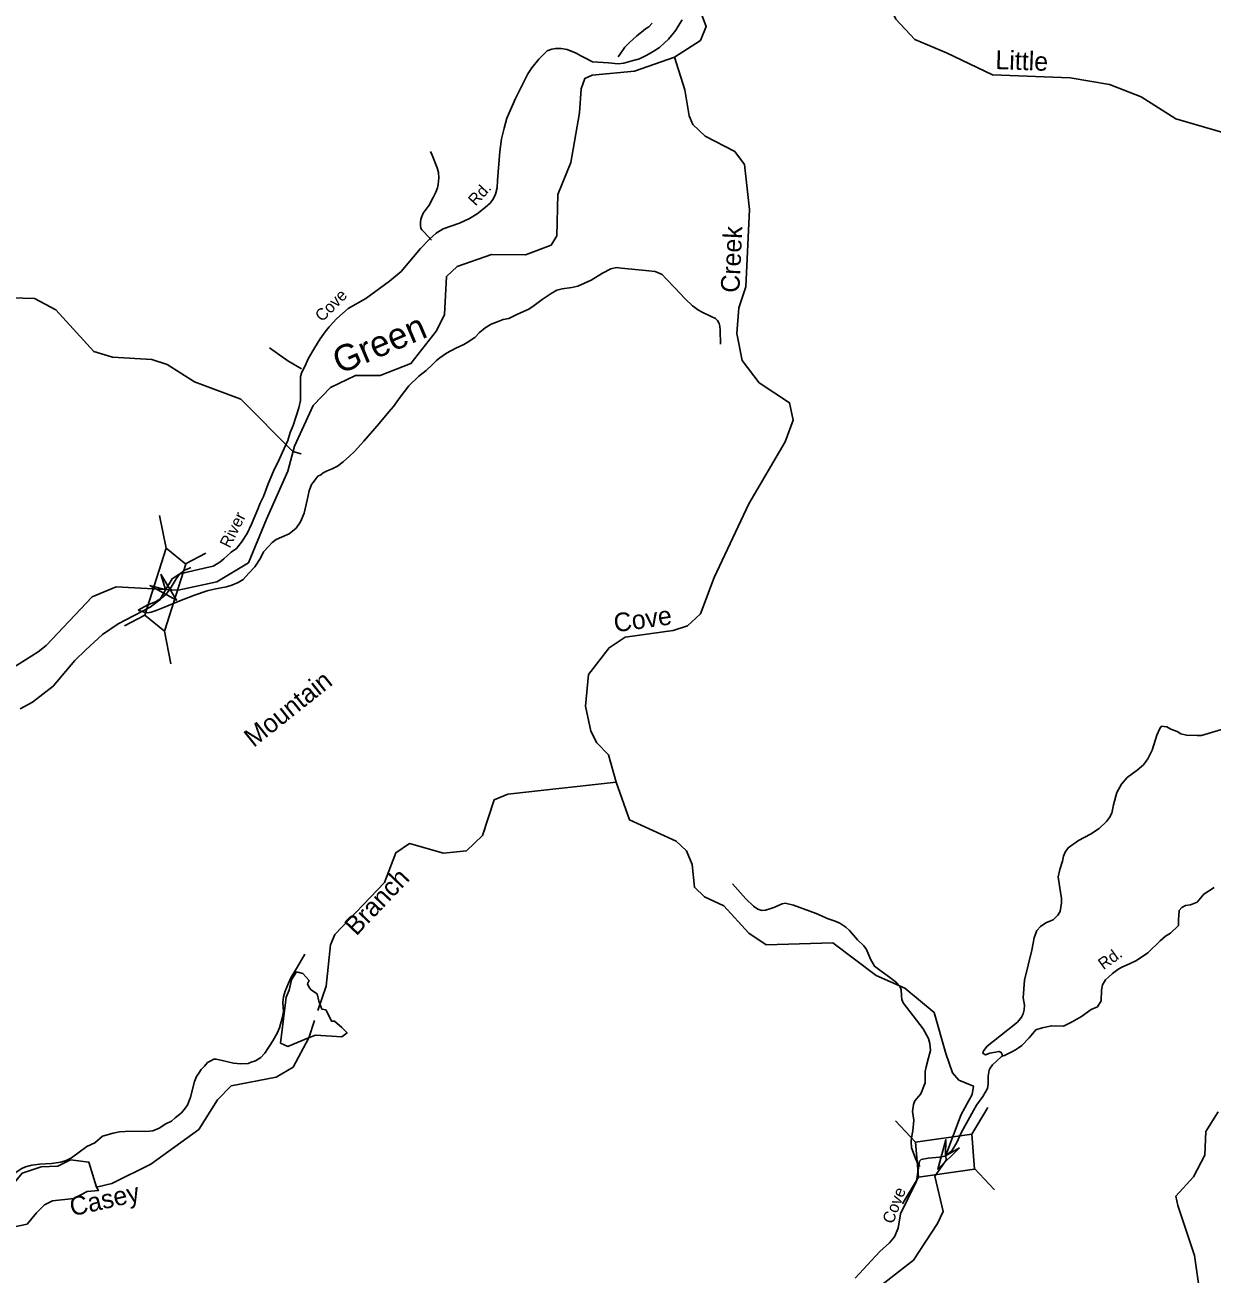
# Model space of a CAD drawing. Extents: x 990631 to 1056237, y 535999 to 585651.
# Drawn here: x 1012421 to 1021960, y 565608 to 575643 of the extents above; entities that cross this region are included whole.
import ezdxf

# ---------------------------------------------------------------- set-up
doc = ezdxf.new("R2010")
doc.units = 0
for name, color, linetype in [('Exist Geographical Mountain Summit Label', 7, 'Continuous'), ('Exist Hydrographic Creek Single Shore', 7, 'Continuous'), ('Exist Hydrographic Creek Single Shore Label', 7, 'Continuous'), ('Exist Hydrographic Pond Over 1500 Sq Ft', 7, 'Continuous'), ('Exist Hydrographic Pond Under 1500 Sq Ft', 7, 'Continuous'), ('Exist Hydrographic River Shore', 7, 'Continuous'), ('Exist Hydrographic River Shore Label', 7, 'Continuous'), ('Exist Road Non-System Type 51', 7, 'Continuous'), ('Exist Road Secondary Structure Standard Bridge Attributed CELL', 7, 'Continuous'), ('Exist Road Secondary Structure Standard Bridge CELL', 7, 'Continuous'), ('Exist Road Secondary Type 41 Attributed', 7, 'Continuous'), ('Exist Road Secondary Type 51 Attributed', 7, 'Continuous'), ('Exist Road Secondary Type 51 Label', 7, 'Continuous')]:
    doc.layers.add(name, color=color, linetype=linetype)

msp = doc.modelspace()

# ---------------------------------------------------------------- linework, layer by layer
at = {"layer": 'Exist Hydrographic Creek Single Shore'}
for points in [[(1023226, 574096), (1023161, 574140), (1023081, 574234), (1022486, 574403), (1022213, 574731), (1021668, 574889), (1021391, 575065), (1021135, 575166), (1020820, 575218), (1020196, 575241), (1019826, 575419), (1019573, 575526), (1019420, 575689), (1019334, 575871), (1019301, 576117), (1019331, 576173), (1019367, 576200), (1019424, 576326), (1019400, 576353), (1019307, 576346), (1019264, 576419), (1019268, 576481)], [(1017171, 569561), (1017111, 569779), (1017015, 569876), (1016968, 569969), (1016924, 570170), (1016950, 570426), (1017115, 570639), (1017243, 570725), (1017629, 570779), (1017746, 570817), (1017850, 570913), (1017960, 571203), (1018238, 571795), (1018530, 572294), (1018594, 572467), (1018565, 572608), (1018320, 572768), (1018184, 572948), (1018142, 573165), (1018157, 573371), (1018213, 573538), (1018242, 574161), (1018204, 574523), (1018124, 574626), (1017886, 574749), (1017789, 574843), (1017758, 574912), (1017723, 575123), (1017640, 575384)], [(1014641, 572198), (1014574, 572216), (1014155, 572638), (1013784, 572777), (1013564, 572916), (1013440, 572955), (1013124, 572974), (1012975, 573020), (1012670, 573354), (1012497, 573446), (1012023, 573459)], [(1014774, 567726), (1014840, 567921), (1014876, 568252), (1014912, 568337), (1015309, 568755), (1015401, 568993), (1015512, 569066), (1015784, 568989), (1015968, 569008), (1016097, 569130), (1016190, 569417), (1016300, 569464), (1017171, 569561)], [(1017782, 568899), (1017736, 569008), (1017655, 569085), (1017278, 569257), (1017171, 569561)], [(1014774, 567726), (1014840, 567921), (1014876, 568252), (1014912, 568337), (1015309, 568755), (1015401, 568993), (1015512, 569066), (1015784, 568989), (1015968, 569008), (1016097, 569130), (1016115, 569184)], [(1017782, 568899), (1017736, 569008), (1017655, 569085), (1017438, 569184)], [(1019174, 565382), (1019210, 565447), (1019561, 565719), (1019754, 566014), (1019799, 566111), (1019733, 566394), (1019823, 566522), (1019820, 566562), (1019943, 566890), (1020033, 567051), (1020043, 567118), (1019926, 567166), (1019875, 567224), (1019820, 567381), (1019727, 567708), (1019492, 567906), (1019262, 568006), (1018912, 568269), (1018378, 568254), (1018239, 568348), (1018038, 568566), (1017882, 568638), (1017801, 568715), (1017782, 568899)], [(1019174, 565382), (1019210, 565447), (1019561, 565719), (1019754, 566014), (1019799, 566111), (1019733, 566394), (1019823, 566522), (1019820, 566562), (1019943, 566890), (1020033, 567051), (1020043, 567118), (1019926, 567166), (1019875, 567224), (1019820, 567381), (1019727, 567708), (1019492, 567906), (1019262, 568006), (1018912, 568269), (1018378, 568254), (1018239, 568348), (1018038, 568566), (1017882, 568638), (1017801, 568715), (1017782, 568899)], [(1014701, 567507), (1014747, 567646)], [(1014701, 567507), (1014747, 567646)], [(1012996, 566307), (1013119, 566335), (1013433, 566492), (1013817, 566770), (1013967, 567007), (1014079, 567119), (1014440, 567191), (1014576, 567270), (1014701, 567507)], [(1012996, 566307), (1013119, 566335), (1013433, 566492), (1013817, 566770), (1013967, 567007), (1014079, 567119), (1014440, 567191), (1014576, 567270), (1014701, 567507)]]:
    msp.add_lwpolyline(points, dxfattribs=at)
at = {"layer": 'Exist Hydrographic Pond Over 1500 Sq Ft'}
msp.add_lwpolyline([(1014475, 567463), (1014533, 567437), (1014698, 567507), (1014755, 567526), (1014883, 567520), (1014966, 567514), (1015010, 567545), (1014966, 567590), (1014908, 567641), (1014883, 567641), (1014864, 567686), (1014838, 567730), (1014806, 567737), (1014781, 567800), (1014768, 567858), (1014724, 567889), (1014704, 567909), (1014692, 567940), (1014704, 567966), (1014654, 568023), (1014603, 568036), (1014564, 567972), (1014545, 567889), (1014520, 567832)], close=True, dxfattribs=at)
at = {"layer": 'Exist Hydrographic Pond Under 1500 Sq Ft'}
msp.add_lwpolyline([(1012996, 566307), (1012934, 566507), (1012788, 566526), (1012686, 566475), (1012552, 566469), (1012399, 566418), (1012323, 566328), (1012227, 566284), (1012138, 566182), (1012132, 566099), (1012176, 566086), (1012221, 566125), (1012272, 566118), (1012240, 566074), (1012234, 566029), (1012285, 565984), (1012323, 565984), (1012438, 566010), (1012514, 566099), (1012578, 566163), (1012641, 566195), (1012813, 566214), (1012921, 566271), (1013011, 566278)], close=True, dxfattribs=at)
at = {"layer": 'Exist Hydrographic River Shore'}
for points in [[(1017640, 575384), (1017849, 575518), (1017896, 575631), (1017849, 575751), (1017884, 575838), (1018048, 576021), (1018164, 576082)], [(1014588, 572258), (1014738, 572585), (1014876, 572730), (1015077, 572826), (1015276, 572826), (1015522, 572922), (1015727, 573185), (1015793, 573318), (1015807, 573623), (1015893, 573703), (1016170, 573799), (1016443, 573796), (1016649, 573875), (1016696, 573948), (1016702, 574280), (1016808, 574539), (1016877, 574937), (1016891, 575130), (1016920, 575213), (1016980, 575239), (1017318, 575273), (1017640, 575384)], [(1012272, 570446), (1012528, 570607), (1012591, 570659), (1012962, 571050), (1013154, 571130), (1013652, 571103), (1013964, 571169), (1014216, 571322), (1014362, 571674), (1014534, 572059), (1014588, 572258)]]:
    msp.add_lwpolyline(points, dxfattribs=at)
at = {"layer": 'Exist Road Non-System Type 51'}
for points in [[(1017462, 575657), (1017433, 575628), (1017407, 575611), (1017374, 575586), (1017339, 575555), (1017277, 575499), (1017242, 575465), (1017202, 575406), (1017189, 575386)], [(1015687, 573915), (1015625, 573980), (1015610, 573998), (1015602, 574010), (1015599, 574030), (1015598, 574060), (1015603, 574084), (1015622, 574130), (1015668, 574196), (1015701, 574257), (1015722, 574301), (1015737, 574334), (1015742, 574362), (1015746, 574416), (1015743, 574458), (1015734, 574494), (1015692, 574596), (1015679, 574626)], [(1018009, 573079), (1018008, 573190), (1018006, 573222), (1018000, 573244), (1017985, 573268), (1017970, 573285), (1017936, 573302), (1017863, 573335), (1017834, 573351), (1017785, 573387), (1017727, 573443), (1017643, 573532), (1017572, 573606), (1017541, 573639), (1017484, 573663), (1017434, 573669), (1017298, 573681), (1017211, 573690), (1017175, 573694), (1017130, 573683), (1017061, 573649), (1016971, 573592), (1016918, 573568), (1016864, 573544), (1016815, 573534), (1016739, 573522), (1016696, 573512), (1016649, 573485), (1016578, 573437), (1016512, 573390), (1016469, 573359), (1016380, 573320), (1016309, 573286), (1016264, 573278), (1016210, 573256), (1016167, 573239), (1016118, 573209), (1016073, 573172), (1016035, 573133), (1015974, 573093), (1015947, 573076), (1015882, 573046), (1015809, 573005), (1015756, 572970), (1015729, 572947), (1015692, 572913), (1015646, 572868), (1015587, 572822), (1015506, 572743), (1015435, 572653), (1015382, 572579), (1015345, 572536), (1015268, 572440), (1015145, 572298), (1015070, 572217), (1015029, 572178), (1014977, 572132), (1014932, 572099), (1014889, 572077), (1014849, 572062), (1014818, 572045), (1014798, 572030), (1014775, 572019), (1014757, 571997), (1014736, 571968), (1014723, 571950), (1014705, 571899), (1014689, 571825), (1014665, 571720), (1014635, 571651), (1014599, 571600), (1014572, 571577), (1014544, 571554), (1014481, 571528), (1014440, 571509), (1014407, 571485), (1014380, 571457), (1014339, 571409), (1014313, 571360), (1014269, 571289), (1014221, 571240), (1014173, 571188), (1014134, 571163), (1014084, 571143), (1014041, 571130), (1013940, 571110), (1013884, 571098), (1013783, 571063), (1013651, 571011), (1013543, 570965), (1013476, 570939), (1013436, 570925), (1013408, 570919), (1013386, 570922), (1013330, 570942)], [(1014387, 573048), (1014532, 572945), (1014644, 572881)], [(1013330, 570942), (1013408, 570984), (1013469, 571009), (1013520, 571040), (1013555, 571071), (1013588, 571114), (1013635, 571194), (1013664, 571231), (1013685, 571248), (1013703, 571262), (1013738, 571277), (1013754, 571284)], [(1020279, 567360), (1020266, 567388), (1020249, 567397), (1020174, 567383), (1020140, 567370), (1020122, 567379), (1020118, 567385), (1020121, 567393), (1020127, 567405), (1020154, 567438), (1020319, 567570), (1020397, 567632), (1020430, 567671), (1020441, 567698), (1020450, 567732), (1020453, 567768), (1020443, 567826), (1020452, 567968), (1020512, 568210), (1020531, 568310), (1020553, 568369), (1020581, 568400), (1020625, 568429), (1020656, 568442), (1020684, 568455), (1020722, 568492), (1020739, 568521), (1020751, 568591), (1020750, 568625), (1020735, 568727), (1020724, 568800), (1020736, 568859), (1020758, 568925), (1020767, 568964), (1020780, 568998), (1020804, 569033), (1020888, 569092), (1020983, 569143), (1021053, 569187), (1021113, 569245), (1021136, 569276), (1021155, 569312), (1021167, 569377), (1021195, 569477), (1021233, 569545), (1021279, 569596), (1021359, 569655), (1021408, 569700), (1021444, 569748), (1021478, 569817), (1021516, 569938), (1021540, 569991), (1021555, 570009), (1021573, 570008), (1021597, 570005), (1021628, 569986), (1021679, 569967), (1021709, 569948), (1021756, 569938), (1021840, 569935), (1021876, 569934), (1021955, 569959), (1022036, 569983)], [(1020279, 567360), (1020266, 567388), (1020249, 567397), (1020174, 567383), (1020140, 567370), (1020122, 567379), (1020118, 567385), (1020121, 567393), (1020127, 567405), (1020154, 567438), (1020319, 567570), (1020397, 567632), (1020430, 567671), (1020441, 567698), (1020450, 567732), (1020453, 567768), (1020443, 567826), (1020452, 567968), (1020512, 568210), (1020531, 568310), (1020553, 568369), (1020581, 568400), (1020625, 568429), (1020656, 568442), (1020684, 568455), (1020722, 568492), (1020739, 568521), (1020751, 568591), (1020750, 568625), (1020735, 568727), (1020724, 568800), (1020736, 568859), (1020758, 568925), (1020767, 568964), (1020780, 568998), (1020804, 569033), (1020888, 569092), (1020983, 569143), (1021048, 569184)], [(1018106, 568743), (1018214, 568623), (1018274, 568563), (1018310, 568540), (1018341, 568529), (1018373, 568532), (1018406, 568543), (1018440, 568554), (1018505, 568582), (1018529, 568587), (1018597, 568572), (1018779, 568504), (1018875, 568463), (1018931, 568443), (1018970, 568428), (1019017, 568396), (1019046, 568368), (1019112, 568293), (1019162, 568244), (1019183, 568215), (1019215, 568138), (1019247, 568081), (1019302, 568041), (1019368, 567992), (1019427, 567947), (1019452, 567920), (1019463, 567891), (1019465, 567847), (1019468, 567815), (1019477, 567787), (1019640, 567577), (1019682, 567500), (1019693, 567461), (1019697, 567405), (1019681, 567344), (1019662, 567274), (1019655, 567236), (1019654, 567192), (1019654, 567144), (1019621, 567055), (1019571, 567001), (1019560, 566971), (1019552, 566913), (1019564, 566845), (1019557, 566759), (1019545, 566702), (1019542, 566672), (1019544, 566623), (1019583, 566522), (1019611, 566471)], [(1012424, 566470), (1012477, 566484), (1012541, 566491), (1012635, 566497), (1012708, 566508), (1012753, 566521), (1012794, 566543), (1012917, 566632), (1012983, 566663), (1013045, 566715), (1013130, 566740), (1013180, 566750), (1013227, 566754), (1013421, 566756), (1013449, 566759), (1013500, 566781), (1013553, 566814), (1013598, 566836), (1013629, 566863), (1013678, 566904), (1013701, 566929), (1013726, 566964), (1013750, 567029), (1013782, 567154), (1013800, 567196), (1013817, 567221), (1013838, 567251), (1013863, 567278), (1013889, 567307), (1013910, 567318), (1013938, 567335), (1013956, 567335), (1014006, 567325), (1014097, 567302), (1014155, 567298), (1014214, 567300), (1014238, 567309), (1014274, 567322), (1014315, 567347), (1014348, 567382), (1014414, 567483), (1014448, 567544), (1014465, 567586), (1014488, 567663), (1014498, 567717), (1014494, 567789), (1014498, 567835), (1014511, 567880), (1014539, 567944), (1014557, 567989), (1014610, 568077), (1014669, 568177)], [(1022008, 566911), (1021909, 566754), (1021901, 566564), (1021810, 566390), (1021670, 566233), (1021686, 566159), (1021818, 565756), (1021851, 565533), (1021975, 565327)]]:
    msp.add_lwpolyline(points, dxfattribs=at)
at = {"layer": 'Exist Road Secondary Structure Standard Bridge Attributed CELL'}
for points in [[(1013513, 571232), (1013639, 571023), (1013425, 571141), (1013551, 571108)], [(1019930, 566623), (1019756, 566452), (1019822, 566687), (1019818, 566557)]]:
    msp.add_lwpolyline(points, close=True, dxfattribs=at)
at = {"layer": 'Exist Road Secondary Structure Standard Bridge CELL'}
for p, q in [((1013556, 571439), (1013503, 571701)), ((1013710, 571314), (1013874, 571399)), ((1013220, 570816), (1013384, 570901)), ((1013594, 570510), (1013541, 570773)), ((1020029, 566732), (1020159, 566947)), ((1019417, 566840), (1019578, 566668)), ((1020051, 566457), (1020213, 566284)), ((1019472, 566172), (1019601, 566387))]:
    msp.add_line(p, q, dxfattribs=at)
for points in [[(1013384, 570901), (1013556, 571440), (1013713, 571311), (1013541, 570773)], [(1019578, 566668), (1020029, 566733), (1020052, 566452), (1019601, 566387)]]:
    msp.add_lwpolyline(points, close=True, dxfattribs=at)
at = {"layer": 'Exist Road Secondary Type 41 Attributed'}
msp.add_lwpolyline([(1011701, 565593), (1011784, 565738), (1011833, 565845), (1011885, 565952), (1011932, 566052), (1011967, 566094), (1012074, 566186), (1012142, 566268), (1012190, 566320), (1012228, 566347), (1012276, 566376), (1012316, 566402), (1012357, 566433), (1012396, 566457), (1012424, 566470)], dxfattribs=at)
at = {"layer": 'Exist Road Secondary Type 51 Attributed'}
for points in [[(1013549, 571105), (1013605, 571194), (1013660, 571232), (1013724, 571247), (1013780, 571260), (1013851, 571275), (1013934, 571296), (1013987, 571328), (1014018, 571355), (1014048, 571381), (1014077, 571407), (1014120, 571437), (1014161, 571487), (1014206, 571558), (1014242, 571633), (1014293, 571754), (1014312, 571800), (1014337, 571856), (1014357, 571906), (1014374, 571957), (1014417, 572058), (1014466, 572157), (1014504, 572240), (1014533, 572305), (1014553, 572368), (1014576, 572425), (1014601, 572500), (1014621, 572567), (1014636, 572627), (1014636, 572698), (1014635, 572773), (1014635, 572819), (1014646, 572854), (1014669, 572898), (1014699, 572965), (1014749, 573052), (1014793, 573121), (1014832, 573178), (1014865, 573218), (1014926, 573286), (1015017, 573365), (1015160, 573445), (1015351, 573586), (1015445, 573663), (1015598, 573846), (1015672, 573922), (1015726, 573970), (1015781, 574005), (1015913, 574051), (1015992, 574088), (1016054, 574125), (1016118, 574177), (1016161, 574213), (1016186, 574250), (1016203, 574283), (1016215, 574335), (1016219, 574394), (1016238, 574627), (1016250, 574728), (1016273, 574815), (1016294, 574894), (1016363, 575052), (1016461, 575251), (1016495, 575299), (1016551, 575368), (1016593, 575412), (1016616, 575435), (1016656, 575449), (1016686, 575455), (1016729, 575454), (1016777, 575446), (1016849, 575417), (1016889, 575394), (1016924, 575376), (1016981, 575346), (1017109, 575338), (1017189, 575330), (1017234, 575336), (1017290, 575351), (1017360, 575372), (1017419, 575401), (1017468, 575429), (1017519, 575462), (1017560, 575500), (1017592, 575530), (1017629, 575574), (1017651, 575602), (1017671, 575634), (1017703, 575683)], [(1012383, 570149), (1012482, 570203), (1012648, 570331), (1012822, 570536), (1012909, 570624), (1013045, 570745), (1013170, 570833), (1013426, 570967), (1013505, 571024), (1013549, 571105)], [(1020042, 566921), (1020068, 566966), (1020119, 567035), (1020155, 567100), (1020160, 567135), (1020162, 567199), (1020168, 567247), (1020178, 567263), (1020195, 567288), (1020228, 567319), (1020269, 567356), (1020279, 567360), (1020292, 567365), (1020351, 567393), (1020381, 567410), (1020406, 567425), (1020432, 567444), (1020490, 567505), (1020543, 567570), (1020595, 567586), (1020672, 567603), (1020767, 567600), (1020835, 567635), (1020912, 567678), (1020990, 567733), (1021039, 567755), (1021069, 567804), (1021073, 567890), (1021081, 567931), (1021104, 567973), (1021129, 567992), (1021159, 568023), (1021202, 568054), (1021235, 568073), (1021297, 568101), (1021352, 568127), (1021445, 568190), (1021543, 568285), (1021586, 568323), (1021625, 568347), (1021691, 568409), (1021691, 568450), (1021695, 568529), (1021718, 568554), (1021746, 568568), (1021786, 568575), (1021840, 568597), (1021893, 568660), (1021976, 568714)], [(1020042, 566921), (1020068, 566966), (1020119, 567035), (1020155, 567100), (1020160, 567135), (1020162, 567199), (1020168, 567247), (1020178, 567263), (1020195, 567288), (1020228, 567319), (1020269, 567356), (1020279, 567360), (1020292, 567365), (1020351, 567393), (1020381, 567410), (1020406, 567425), (1020432, 567444), (1020490, 567505), (1020543, 567570), (1020595, 567586), (1020672, 567603), (1020767, 567600), (1020835, 567635), (1020912, 567678), (1020990, 567733), (1021039, 567755), (1021069, 567804), (1021073, 567890), (1021081, 567931), (1021104, 567973), (1021129, 567992), (1021159, 568023), (1021202, 568054), (1021235, 568073), (1021249, 568079)], [(1019093, 565576), (1019290, 565788), (1019369, 565859), (1019409, 565908), (1019437, 565976), (1019457, 566091), (1019584, 566354), (1019609, 566516), (1019623, 566528), (1019678, 566539), (1019770, 566546), (1019816, 566556), (1019841, 566576), (1019868, 566599), (1019908, 566664), (1019945, 566742), (1020042, 566921)]]:
    msp.add_lwpolyline(points, dxfattribs=at)

# ---------------------------------------------------------------- texts
at = {"layer": 'Exist Geographical Mountain Summit Label'}
msp.add_text('Mountain', height=150, rotation=38.5473, dxfattribs=at).set_placement((1014258, 569834))
at = {"layer": 'Exist Hydrographic Creek Single Shore Label'}
for s, rotation, p in [('Little', 357.9415, (1020217, 575289)), ('Creek', 87.3241, (1018161, 573489)), ('Cove', 8.0533, (1017163, 570763)), ('Branch', 46.4785, (1015083, 568319)), ('Branch', 46.4785, (1015083, 568319)), ('Casey', 12.7784, (1012799, 566071)), ('Casey', 12.7784, (1012799, 566071))]:
    msp.add_text(s, height=150, rotation=rotation, dxfattribs=at).set_placement(p)
at = {"layer": 'Exist Hydrographic River Shore Label'}
msp.add_text('Green', height=210, rotation=23.0548, dxfattribs=at).set_placement((1014950, 572835))
at = {"layer": 'Exist Road Secondary Type 51 Label'}
for s, rotation, p in [('Rd.', 47.3691, (1016042, 574183)), ('Cove', 45.2275, (1014809, 573253)), ('River', 63.4143, (1014066, 571434)), ('Rd.', 35.9632, (1021088, 568048)), ('Rd.', 35.9632, (1021088, 568048)), ('Cove', 69.0743, (1019396, 566005)), ('Cove', 69.0743, (1019396, 566005))]:
    msp.add_text(s, height=95, rotation=rotation, dxfattribs=at).set_placement(p)

doc.saveas('drawing.dxf')
